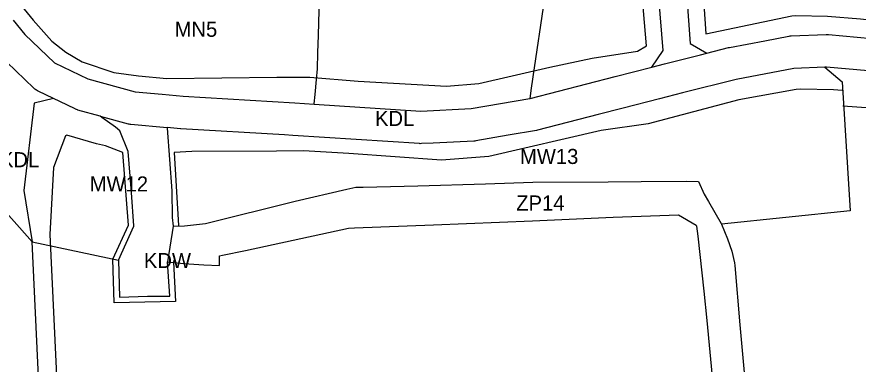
# Model space of a CAD drawing. Extents: x 7428103 to 7431580, y 5545880 to 5549002.
# Drawn here: x 7429340.3 to 7429649.7, y 5547931 to 5548058.7 of the extents above; entities that cross this region are included whole.
import ezdxf

# ---------------------------------------------------------------- set-up
doc = ezdxf.new("R2010")
doc.units = 0
for name, color, linetype in [('CZ_L_linie rozgraniczające tereny o różnym przeznaczeniu oraz różnych warunkach ich zabudowy i zagospodarowania', 7, 'Continuous'), ('CZ_L_maksymalne nieprzekraczalne linie zabudowy', 7, 'Continuous'), ('CZ_L_opisy_linie rozgraniczające tereny o różnym przeznaczeniu oraz różnych warunkach ich zabudowy i zagospodarowania', 7, 'Continuous')]:
    doc.layers.add(name, color=color, linetype=linetype)

msp = doc.modelspace()

# ---------------------------------------------------------------- linework, layer by layer
at = {"layer": 'CZ_L_linie rozgraniczające tereny o różnym przeznaczeniu oraz różnych warunkach ich zabudowy i zagospodarowania'}
for p, q in [((7429578.02, 5548046.38), (7429574.06, 5548092.42)), ((7429584.88, 5548089.06), (7429587.91, 5548048.88)), ((7429451.24, 5548052), (7429451.66, 5548065.75)), ((7429533.91, 5548062.3), (7429530.58, 5548039.93)), ((7429338.98, 5548057.54), (7429343.25, 5548052.27)), ((7429343.25, 5548052.27), (7429354.19, 5548041.8)), ((7429451.03, 5548045.49), (7429451.24, 5548052)), ((7429615.37, 5548049.93), (7429624.18, 5548051.61)), ((7429624.18, 5548051.61), (7429624.28, 5548051.63)), ((7429624.28, 5548051.63), (7429624.67, 5548051.69)), ((7429624.67, 5548051.69), (7429625.06, 5548051.71)), ((7429625.06, 5548051.71), (7429637.96, 5548052.24)), ((7429637.96, 5548052.24), (7429638.35, 5548052.24)), ((7429638.35, 5548052.24), (7429638.74, 5548052.22)), ((7429638.74, 5548052.22), (7429654.54, 5548050.78)), ((7429587.91, 5548048.88), (7429594.06, 5548045.36)), ((7429594.06, 5548045.36), (7429602.03, 5548047.38)), ((7429602.03, 5548047.38), (7429602.09, 5548047.4)), ((7429602.09, 5548047.4), (7429602.38, 5548047.46)), ((7429602.38, 5548047.46), (7429615.37, 5548049.93)), ((7429450.85, 5548039.57), (7429451.03, 5548045.49)), ((7429573.8, 5548040.21), (7429578.02, 5548046.38)), ((7429588.29, 5548043.89), (7429591.7, 5548044.76)), ((7429591.7, 5548044.76), (7429594.06, 5548045.36)), ((7429346.57, 5548032.47), (7429336.61, 5548042.02)), ((7429354.19, 5548041.8), (7429366.46, 5548035.87)), ((7429573.8, 5548040.21), (7429578.45, 5548041.39)), ((7429578.45, 5548041.39), (7429588.29, 5548043.89)), ((7429450.48, 5548035.64), (7429450.85, 5548039.57)), ((7429530.58, 5548039.93), (7429529.5, 5548032.48)), ((7429560.29, 5548036.78), (7429573.8, 5548040.21)), ((7429625.99, 5548039.74), (7429604.8, 5548035.71)), ((7429637.39, 5548040.2), (7429625.99, 5548039.74)), ((7429638.05, 5548040.23), (7429637.39, 5548040.2)), ((7429637.39, 5548040.2), (7429643.84, 5548034.85)), ((7429653.39, 5548038.84), (7429638.05, 5548040.23)), ((7429366.46, 5548035.87), (7429383.88, 5548031.12)), ((7429450.05, 5548030.17), (7429450.48, 5548035.64)), ((7429529.06, 5548028.73), (7429560.27, 5548036.78)), ((7429560.27, 5548036.78), (7429560.29, 5548036.78)), ((7429604.8, 5548035.71), (7429585.14, 5548030.71)), ((7429346.66, 5548032.39), (7429346.57, 5548032.47)), ((7429346.95, 5548032.14), (7429346.66, 5548032.39)), ((7429347.27, 5548031.9), (7429346.95, 5548032.14)), ((7429347.29, 5548031.88), (7429347.27, 5548031.9)), ((7429347.59, 5548031.69), (7429347.29, 5548031.88)), ((7429529.5, 5548032.48), (7429528.96, 5548028.71)), ((7429643.84, 5548034.85), (7429646.73, 5547987.36)), ((7429347.94, 5548031.49), (7429347.59, 5548031.69)), ((7429348.12, 5548031.4), (7429347.94, 5548031.49)), ((7429353.82, 5548028.65), (7429348.12, 5548031.4)), ((7429383.88, 5548031.12), (7429393.77, 5548030.23)), ((7429393.77, 5548030.23), (7429393.77, 5548030.23)), ((7429393.77, 5548030.23), (7429401.44, 5548029.54)), ((7429401.44, 5548029.54), (7429442.58, 5548027.06)), ((7429449.65, 5548026.74), (7429450.05, 5548030.17)), ((7429507.41, 5548024.97), (7429528.96, 5548028.71)), ((7429528.96, 5548028.71), (7429529.06, 5548028.73)), ((7429585.14, 5548030.71), (7429576.6, 5548028.54)), ((7429346.7, 5548026.92), (7429342.88, 5547994.84)), ((7429353.82, 5548028.65), (7429346.7, 5548026.92)), ((7429356.15, 5548027.53), (7429353.82, 5548028.65)), ((7429361.74, 5548024.83), (7429356.15, 5548027.53)), ((7429442.58, 5548027.06), (7429442.6, 5548027.06)), ((7429442.6, 5548027.06), (7429449.6, 5548026.6)), ((7429449.6, 5548026.6), (7429449.65, 5548026.74)), ((7429449.6, 5548026.6), (7429488.86, 5548024.07)), ((7429576.6, 5548028.54), (7429563.26, 5548025.16)), ((7429361.92, 5548024.75), (7429361.74, 5548024.83)), ((7429362.28, 5548024.6), (7429361.92, 5548024.75)), ((7429362.65, 5548024.48), (7429362.28, 5548024.6)), ((7429362.77, 5548024.44), (7429362.65, 5548024.48)), ((7429370.91, 5548022.22), (7429362.77, 5548024.44)), ((7429488.86, 5548024.07), (7429507.41, 5548024.97)), ((7429554.04, 5548022.78), (7429531.83, 5548017.05)), ((7429554.05, 5548022.78), (7429554.04, 5548022.78)), ((7429563.26, 5548025.16), (7429554.05, 5548022.78)), ((7429370.91, 5548022.22), (7429381.24, 5548019.4)), ((7429381.24, 5548019.4), (7429381.5, 5548019.34)), ((7429381.5, 5548019.34), (7429381.88, 5548019.26)), ((7429381.88, 5548019.26), (7429382.27, 5548019.22)), ((7429382.27, 5548019.22), (7429382.28, 5548019.22)), ((7429382.28, 5548019.22), (7429395.57, 5548018.02)), ((7429395.57, 5548018.02), (7429395.57, 5548017.83)), ((7429400.46, 5548017.58), (7429395.57, 5548018.02)), ((7429395.57, 5548017.83), (7429397.3, 5547994.66)), ((7429400.63, 5548017.56), (7429400.46, 5548017.58)), ((7429438.71, 5548015.27), (7429400.63, 5548017.56)), ((7429531.36, 5548016.95), (7429520.97, 5548015.14)), ((7429531.74, 5548017.03), (7429531.36, 5548016.95)), ((7429531.83, 5548017.05), (7429531.74, 5548017.03)), ((7429438.72, 5548015.27), (7429438.71, 5548015.27)), ((7429441.85, 5548015.08), (7429438.72, 5548015.27)), ((7429488.42, 5548012.07), (7429441.85, 5548015.08)), ((7429520.97, 5548015.14), (7429509.1, 5548013.08)), ((7429488.66, 5548012.06), (7429488.42, 5548012.07)), ((7429489.1, 5548012.07), (7429488.66, 5548012.06)), ((7429493.43, 5548012.28), (7429489.1, 5548012.07)), ((7429508.36, 5548013), (7429493.43, 5548012.28)), ((7429493.43, 5548012.28), (7429493.43, 5548012.28)), ((7429508.7, 5548013.02), (7429508.36, 5548013)), ((7429509.09, 5548013.08), (7429508.7, 5548013.02)), ((7429509.1, 5548013.08), (7429509.09, 5548013.08)), ((7429512.71, 5547997.32), (7429530.05, 5547997.85)), ((7429530.05, 5547997.85), (7429557.79, 5547998.07)), ((7429557.79, 5547998.07), (7429569.92, 5547998.14)), ((7429569.92, 5547998.14), (7429586.39, 5547998.22)), ((7429586.39, 5547998.22), (7429590.97, 5547998.21)), ((7429590.97, 5547998.21), (7429593.07, 5547993.54)), ((7429342.88, 5547994.84), (7429345.98, 5547976.01)), ((7429397.3, 5547994.66), (7429397.5, 5547984.96)), ((7429442.68, 5547990.93), (7429461.7, 5547995.28)), ((7429461.7, 5547995.28), (7429464.97, 5547996.03)), ((7429464.97, 5547996.03), (7429467.67, 5547996.1)), ((7429467.67, 5547996.1), (7429487.81, 5547996.62)), ((7429487.81, 5547996.62), (7429512.71, 5547997.32)), ((7429593.07, 5547993.54), (7429594.65, 5547990.8)), ((7429409.76, 5547982.75), (7429442.68, 5547990.93)), ((7429594.65, 5547990.8), (7429599.31, 5547982.72)), ((7429337.38, 5547985.6), (7429341.26, 5547981.26)), ((7429559.65, 5547985.02), (7429583.58, 5547985.93)), ((7429583.58, 5547985.93), (7429590.15, 5547982.05)), ((7429646.73, 5547987.36), (7429599.4, 5547982.5)), ((7429397.5, 5547984.96), (7429397.82, 5547981.78)), ((7429402.01, 5547981.87), (7429409.76, 5547982.75)), ((7429493.52, 5547982.19), (7429529.88, 5547983.73)), ((7429529.88, 5547983.73), (7429559.65, 5547985.02)), ((7429599.31, 5547982.72), (7429599.4, 5547982.5)), ((7429599.4, 5547982.5), (7429601.59, 5547977.01)), ((7429341.26, 5547981.26), (7429345.98, 5547976.01)), ((7429397.82, 5547981.78), (7429395.75, 5547968.65)), ((7429397.82, 5547981.78), (7429402.01, 5547981.87)), ((7429424.37, 5547972.83), (7429462.31, 5547981.03)), ((7429462.31, 5547981.03), (7429464.52, 5547981.17)), ((7429464.52, 5547981.17), (7429493.52, 5547982.19)), ((7429590.15, 5547982.05), (7429590.19, 5547981.76)), ((7429590.19, 5547981.76), (7429590.75, 5547978.1)), ((7429590.75, 5547978.1), (7429592.98, 5547957.86)), ((7429601.59, 5547977.01), (7429603.24, 5547972.5)), ((7429350.22, 5547883.45), (7429345.98, 5547976.01)), ((7429345.98, 5547976.01), (7429377.7, 5547969.21)), ((7429414.81, 5547967.61), (7429414.89, 5547970.79)), ((7429414.89, 5547970.79), (7429415.96, 5547971.02)), ((7429415.96, 5547971.02), (7429424.37, 5547972.83)), ((7429603.24, 5547972.5), (7429604.21, 5547968.25)), ((7429377.7, 5547969.21), (7429378.03, 5547955.59)), ((7429395.75, 5547968.65), (7429395.76, 5547968.62)), ((7429395.76, 5547968.62), (7429401.75, 5547968.05)), ((7429396.57, 5547955.99), (7429395.76, 5547968.62)), ((7429401.75, 5547968.05), (7429409.04, 5547967.47)), ((7429409.04, 5547967.47), (7429414.8, 5547967.25)), ((7429414.8, 5547967.25), (7429414.81, 5547967.61)), ((7429604.21, 5547968.25), (7429604.28, 5547967.25)), ((7429604.28, 5547967.25), (7429606.13, 5547945.39)), ((7429592.98, 5547957.86), (7429594.05, 5547947.07)), ((7429378.03, 5547955.59), (7429388.43, 5547955.98)), ((7429388.43, 5547955.98), (7429396.57, 5547955.99)), ((7429594.05, 5547947.07), (7429596.27, 5547923.71)), ((7429606.13, 5547945.39), (7429607.73, 5547927.86))]:
    msp.add_line(p, q, dxfattribs=at)
for points in [[(7429377.7, 5547969.21), (7429383.38, 5547981.73), (7429383.39, 5547981.82), (7429383.4, 5547981.88), (7429382.46, 5547994.11), (7429381.3, 5548009.24), (7429378.2, 5548016.8), (7429376.59, 5548018.18), (7429371.59, 5548021.73), (7429370.91, 5548022.22)], [(7429377.7, 5547969.21), (7429377.7, 5547969.21)]]:
    msp.add_lwpolyline(points, dxfattribs=at)
at = {"layer": 'CZ_L_maksymalne nieprzekraczalne linie zabudowy'}
for points in [[(7429737.56, 5548266.68), (7429712.6, 5548265.77), (7429657.63, 5548261.19), (7429626.79, 5548257.94), (7429606.97, 5548255.66), (7429606.31, 5548255.44), (7429604.61, 5548253.44), (7429611.04, 5548115.65), (7429608.73, 5548101.41), (7429605.47, 5548096.04), (7429602.01, 5548092.86), (7429597.64, 5548091.02), (7429592.48, 5548090.26), (7429591.2, 5548089.04), (7429593.66, 5548052.51), (7429625.28, 5548059.08), (7429626.81, 5548059.19), (7429638.42, 5548058.91), (7429650.51, 5548058.04), (7429686.57, 5548053.92), (7429706.66, 5548051.95), (7429717.21, 5548051.09), (7429737.76, 5548049.93)], [(7429340.85, 5548064.2), (7429346.35, 5548057.51), (7429353.23, 5548049.82), (7429358.36, 5548045.7), (7429364.4, 5548042.17), (7429375.97, 5548038.21), (7429385.01, 5548037.04), (7429395.45, 5548036.04), (7429435.96, 5548036.53), (7429448.02, 5548036.49), (7429465.85, 5548035.1), (7429498.32, 5548033.26), (7429510.21, 5548034.23), (7429536.34, 5548040.2), (7429551.86, 5548043.57), (7429568.56, 5548046.08), (7429571.86, 5548048), (7429568.03, 5548092.53)], [(7429643.75, 5548031.59), (7429640.58, 5548031.85), (7429628.44, 5548032.16), (7429626.82, 5548032.05), (7429605.74, 5548028.13), (7429572.41, 5548019.42), (7429555.2, 5548016.89), (7429513.82, 5548007.36), (7429496.48, 5548006.06), (7429462.35, 5548008.44), (7429445.74, 5548009.4), (7429435.79, 5548009.25), (7429404.67, 5548009.24), (7429398.24, 5548008.81), (7429399.82, 5547981.97)], [(7429807.79, 5548025.22), (7429785.86, 5548020.87), (7429764.76, 5548017.83), (7429756.34, 5548017.17), (7429740.83, 5548016.75), (7429725.46, 5548016.89), (7429688.59, 5548020.99), (7429654.28, 5548025.17), (7429644.09, 5548025.88)], [(7429398.06, 5547969.24), (7429397.95, 5547968.51), (7429398.7, 5547953.99), (7429376.08, 5547953.52), (7429375.68, 5547969.6), (7429381.37, 5547982.15), (7429379.33, 5548008.77), (7429372.88, 5548011.31), (7429369.61, 5548012.02), (7429358.71, 5548015.17), (7429358.22, 5548014.9), (7429353.84, 5548003.28), (7429352.52, 5547978.68), (7429357.02, 5547882.63), (7429420.25, 5547781.76)]]:
    msp.add_lwpolyline(points, dxfattribs=at)

# ---------------------------------------------------------------- texts
at = {"layer": 'CZ_L_opisy_linie rozgraniczające tereny o różnym przeznaczeniu oraz różnych warunkach ich zabudowy i zagospodarowania'}
for s, p in [('MN5', (7429398.35, 5548051.37)), ('KDL', (7429472.02, 5548018.58)), ('MW13', (7429525.35, 5548004.6)), ('KDL', (7429334.12, 5548003.4)), ('MW12', (7429367.14, 5547994.48)), ('ZP14', (7429523.94, 5547987.46)), ('KDW', (7429387.06, 5547966.31))]:
    msp.add_text(s, height=5.549, dxfattribs=at).set_placement(p)

doc.saveas('drawing.dxf')
